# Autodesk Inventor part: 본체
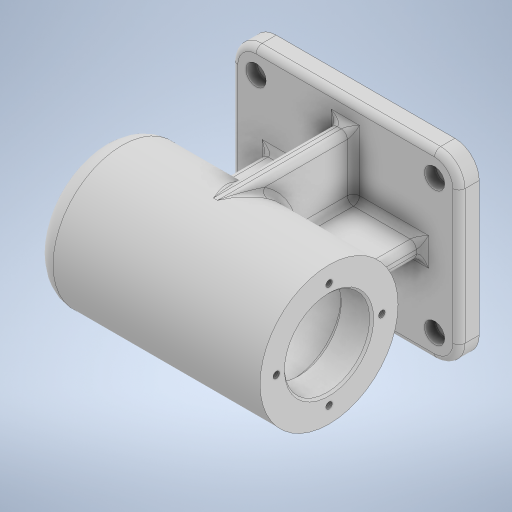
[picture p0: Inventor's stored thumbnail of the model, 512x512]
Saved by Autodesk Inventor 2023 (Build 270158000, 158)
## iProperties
Created: 2026-08
Part Number: 본체
Material: 일반
Document SubType Name: Modeling
Designer: home
Density: 1 g/cm^3
Appearance: 기본값
Author: home
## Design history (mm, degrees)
sketch "스케치1"
  geometry: L1 (0, 0)-(-126.294, 0); L2 (-112, 0)-(-112, 24); L3 (-102, 34)-(0, 34); L4 (0, 34)-(0, 0); L5 (0, 21)-(-15, 21); L6 (-15, 21)-(-15, 24); L7 (-15, 24)-(-69, 24); L8 (-69, 24)-(-69, 21); L9 (-69, 21)-(-81, 21); L10 (-81, 21)-(-81, 17.5); L11 (-81, 17.5)-(-99, 17.5); L12 (-99, 17.5)-(-99, 16); L13 (-99, 16)-(-103, 16); L14 (-103, 16)-(-103, 10.5); L15 (-103, 10.5)-(-106, 10.5); L16 (-106, 10.5)-(-106, 0); A1 r 10 centre (-102, 24) between (-102, 34) and (-112, 24); 1 further point
  constraints: 32 end point, 13 perpendicular, 7 point on line, 2 point on circle, 2 tangent, 1 centre point, 1 horizontal, 1 vertical
  dimensions: "d0" = 68 diameter of L3 L1; "d1" = 112 distance of point (-112, 34) L3.end; "d2" = 42 diameter of L5 L1; "d3" = 48 diameter of L7 L1; "d4" = 35 diameter of L11 L1; "d5" = 32 diameter of L13 L1; "d6" = 21 diameter of L15 L1; "d7" = 15 distance of L5.start L5.end; "d8" = 54 distance of L6.end L7.end; "d9" = 81 distance between parallel lines of L4 L10; "d10" = 18 distance of L10.end L11.end; "d11" = 103 distance between parallel lines of L4 L14; "d12" = 3 distance of L14.end L15.end; "d13" = 10 radius of A1
revolve "회전1" sketch "스케치1" stored, may be unused: angle "d14" = 90 deg
node "작업 평면2"
sketch "스케치3"
  geometry: L1 (-112, 45)-(0, 45); L2 (0, 45)-(0, -45); L3 (0, -45)-(-112, -45); L4 (-112, -45)-(-112, 45); 2 further points
  constraints: 8 end point, 2 parallel, 1 coincident, 1 horizontal, 1 midpoint, 1 perpendicular
  dimensions: "d17" = 112 distance of L2.end L3.end; "d18" = 90 distance of L1.end L2.end
extrude "돌출1" join sketch "스케치3" distance "d19" = 10; taper "d20" = 0 deg
fillet "모깎기1" dims "d21" = 12
sketch "스케치4"
  geometry: L1 (-112, 33)-(-112, -33) reference; L2 (-12, 45)-(-100, 45) reference; L3 (0, -33)-(0, 33) reference; L4 (-100, -45)-(-12, -45) reference; 5 further points
  constraints: 2 horizontal alignment, 2 vertical alignment
  dimensions: "d29" = 12 distance from line of point (-100, 33) L1; "d30" = 12 distance from line of L2 point (-100, 33); "d31" = 12 distance from line of L3 point (-12, 33); "d32" = 12 distance from line of L4 point (-100, -33)
hole "구멍1" sketch "스케치4" at (-100, 33), (-12, 33), (-12, -33), (-100, -33) diameter "d22" = 5.5; stored, may be unused: countersink angle "d26" = 90 deg, drill point angle "d28" = 118 deg; dims "d23" = 6, "d24" = 10, "d25" = 5.5, "d27" = 8
sketch "스케치5"
  geometry: L1 (-94, 4)-(-18, 4); L2 (-18, 4)-(-18, -4); L3 (-18, -4)-(-94, -4); L4 (-94, -4)-(-94, 4); L5 (-100, -45)-(-12, -45) reference; 4 further points
  constraints: 8 end point, 3 midpoint, 2 parallel, 1 horizontal, 1 horizontal alignment, 1 perpendicular, 1 vertical alignment
  dimensions: "d33" = 8 distance of L1.end L2.end; "d34" = 76 distance of L1.start L1.end
extrude "돌출2" join sketch "스케치5" stored distance "d35" = 10; taper "d36" = 0 deg
node "작업 평면3"
sketch "스케치6"
  geometry: L1 (-74, -1)-(-10, -1); L2 (-10, 66)-(-10, 0) reference; L3 (-10, 33)-(-10, -1); L4 (-10, 29)-(-40.236, 29) reference; L5 (-40.236, 29)-(-10, 29); A1 r 34 centre (-74, 33) between (-74, -1) and (-40.236, 29) reference; 3 further points
  constraints: 6 end point, 1 coincident, 1 collinear, 1 horizontal, 1 midpoint, 1 point on circle, 1 point on line, 1 vertical, 1 vertical alignment, 2 other
  dimensions: "d38" = 34 distance from line of L3.start L1
extrude "돌출3" join sketch "스케치6" stored distance "d39" = 8; taper "d40" = 0 deg
sketch "스케치7" dims "d41" = 52
  geometry: L1 (0, 0)-(-26, 0); L2 (-26, 0)-(0, 0); 2 further points
  constraints: 4 end point, 2 coincident, 2 horizontal, 1 horizontal alignment, 2 other
hole "구멍2" sketch "스케치7" at (-26, 0) diameter "d42" = 3.242; stored, may be unused: countersink angle "d46" = 90 deg, drill point angle "d48" = 118 deg; dims "d43" = 8, "d44" = 10, "d45" = 5.5, "d47" = 10
sketch "스케치8"
  geometry: L1 (21.951, 6)-(66.049, 6); L2 (66.049, 6)-(66.049, 0); L3 (66.049, 0)-(21.951, 0); L4 (21.951, 0)-(21.951, 6); L5 (0, 0)-(88, 0) reference; L6 (0, 10)-(88, 10) reference; 4 further points
  constraints: 3 midpoint, 1 horizontal, 1 point on line, 1 vertical alignment, 2 other
  dimensions: "d52" = 3 distance from line of L5 point (66.049, 3)
feature "엠보싱1" sketch "스케치8" dims "d0" = 68, "d1" = 112, "d2" = 42, "d3" = 48, "d4" = 35, "d5" = 32, "d6" = 21, "d7" = 15, "d8" = 54, "d9" = 81, "d10" = 18, "d11" = 103, "d12" = 3, "d13" = 10, "d16" = -74, "d53" = 0.5, "d54" = 0
fillet "모깎기2" dims "d55" = 3
fillet "모깎기3" dims "d56" = 3
fillet "모깎기4" dims "d57" = 3
fillet "모깎기5" dims "d58" = 3
chamfer "모따기1" distance "d59" = 1; stored, may be unused: second distance "d60" = 2, angle "d61" = 45 deg
fillet "모깎기6" dims "d62" = 0.6
fillet "모깎기7" dims "d63" = 3
fillet "모깎기8" dims "d64" = 3
feature "˺耀˼耀˾耀̀耀̂耀̄耀̆耀̈耀" dims "d0" = 68, "d1" = 112, "d2" = 42, "d3" = 48, "d4" = 35, "d5" = 32, "d6" = 21, "d7" = 15, "d8" = 54, "d9" = 81, "d10" = 18, "d11" = 103, "d12" = 3, "d13" = 10, "d14" = 90 deg, "d16" = -74, "d17" = 112, "d18" = 90, "d19" = 10, "d20" = 0, "d21" = 12, "d22" = 5.5, "d23" = 6, "d24" = 10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
node "솔리드1"
mirror "미러1"
pattern_circular "원형 패턴1" dims angle "d50" = 360 deg
feature "A9D066F2-1C7D-4E18-AEED-F7BC21143FA4" dims "d42" = 3.242, "d43" = 8, "d44" = 10, "d45" = 5.5, "d46" = 90 deg, "d47" = 10, "d48" = 118 deg
